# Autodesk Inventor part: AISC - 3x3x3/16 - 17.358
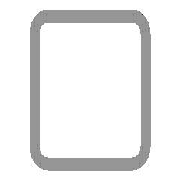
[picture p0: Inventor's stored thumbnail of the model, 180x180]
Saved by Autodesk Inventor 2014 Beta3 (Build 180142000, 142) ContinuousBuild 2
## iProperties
IsCustomPart: 1
Created: 2011-11
Part Number: AISC - 3x3x3/16 - 17.358
Material: Steel, Mild
Description: Tube
Document SubType Name: Modeling
Standard: ANSI
Designer: Thom Tremblay
Standards Organization: ANSI
Language: en-US
Size Designation: 3x3x3/16
Categories: <MemberInstance><Categories><Category DisplayName="Structural Shapes" InternalName="089c4875-fa83-4c05-b084-43b9cc11f5ed" Mnemonic="GRDR"><CategoryParameter Dis
Stock Number: 3x3x3/16
Density: 7.86 g/cm^3
Appearance: Steel
_CCFamilyMember: 9
_CCFamilyDisplayName: ANSI AISC (Square) - Tube
_FrameMemberDoc: Frame Member File
_Version: 15.0.0
_GetPNFromCC: 1
G_L: 17.358 in
G_W: 3.000 in
G_H: 3.000 in
+34C88DA3-0550-4048-8914-D3E873063934+CUTDETAIL3: Cut
+0CA68347-A200-4C89-AB1E-A678EAF8D6F7+CUTDETAIL4: Cut
Author: Thom Tremblay
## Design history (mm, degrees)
node "Start plane"
node "End plane"
node "Driven Length"
  sketch "Sketch3"
    geometry: L1 (0, 0)-(10, 0) reference
    constraints: 2 end point, 1 horizontal
  workplane "Work Plane3"
  sketch "Sketch4"
    geometry: L1 (-2, 0)-(12, 0) reference; L2 (-53.343, 440.904)-(53.343, 440.904) reference
    dimensions: "d19" = 440.90386 distance between parallel lines of L1 L2 (derived)
sketch "Sweep Path"
  geometry: L1 through (609.6, 0) direction (1, 0); 1 other entity
  constraints: 5 horizontal
node "Orientation Work Plane"
feature "Body" dims "d20" = 0
workplane "Work Plane7"
sketch "Sketch7"
  geometry: L1 (-38.6, 38.6)-(38.6, 38.6); L2 (-38.6, -38.6)-(38.6, -38.6)
  constraints: 4 end point
feature "LoftSrf3" sketch "Sketch7" dims "d29" = 0, "d30" = 90 deg, "d31" = 0, "d32" = 90 deg
split "Split3"
workplane "Work Plane8"
sketch "Sketch8"
  geometry: L1 (-38.6, 38.6)-(38.6, 38.6); L2 (-38.6, -38.6)-(38.6, -38.6)
  constraints: 4 end point
feature "LoftSrf4" sketch "Sketch8" dims "d33" = 0, "d34" = 90 deg, "d35" = 0, "d36" = 90 deg
split "Split4"
workplane "Work Plane9"
sketch "Sketch9"
  geometry: L1 (-38.6, 44.506)-(38.6, 44.506); L2 (-38.6, -44.506)-(38.6, -44.506)
  constraints: 4 end point
feature "LoftSrf5" sketch "Sketch9" dims "d37" = 0, "d38" = 90 deg, "d39" = 0, "d40" = 90 deg
split "Split5"
workplane "Work Plane10"
sketch "Sketch10"
  geometry: L1 (-38.6, 44.506)-(38.6, 44.506); L2 (-38.6, -44.506)-(38.6, -44.506)
  constraints: 4 end point
feature "LoftSrf6" sketch "Sketch10" dims "d41" = 0, "d42" = 90 deg, "d43" = 0, "d44" = 90 deg
split "Split6"
body "Solid1"
sketch "Sketch"
  geometry: L1 (-38.1, -28.575)-(-38.1, 28.575); L2 (-28.575, 38.1)-(28.575, 38.1); L3 (38.1, 28.575)-(38.1, -28.575); L4 (28.575, -38.1)-(-28.575, -38.1); L5 (-28.575, 33.337)-(28.575, 33.338); L6 (33.338, 28.575)-(33.338, -28.575); L7 (28.575, -33.337)-(-28.575, -33.338); L8 (-33.338, -28.575)-(-33.338, 28.575); L9 (0, 36.948)-(0, -36.948); L10 (-23.079, 0)-(23.079, 0); A1 r 9.525 centre (-28.575, -28.575) between (-38.1, -28.575) and (-28.575, -38.1); A2 r 9.525 centre (-28.575, 28.575) between (-28.575, 38.1) and (-38.1, 28.575); A3 r 9.525 centre (28.575, 28.575) between (38.1, 28.575) and (28.575, 38.1); A4 r 9.525 centre (28.575, -28.575) between (28.575, -38.1) and (38.1, -28.575); A5 r 4.763 centre (-28.575, 28.575) between (-28.575, 33.337) and (-33.338, 28.575); A6 r 4.763 centre (28.575, 28.575) between (33.338, 28.575) and (28.575, 33.338); A7 r 4.763 centre (28.575, -28.575) between (28.575, -33.337) and (33.338, -28.575); A8 r 4.763 centre (-28.575, -28.575) between (-33.338, -28.575) and (-28.575, -33.338)
  constraints: 20 end point, 16 point on circle, 8 centre point, 8 tangent, 4 parallel, 3 equal radius, 2 perpendicular, 7 other
  dimensions: "d10" = 76.2 distance between parallel lines of L2 L4 (= G_H); "d11" = 76.2 distance between parallel lines of L1 L3 (= G_W); "d12" = 4.7625 distance between parallel lines of L3 L6 (= G_T); "d15" = 38.1 distance between parallel lines of L2 L10 (= 0.5 x d10); "d16" = 38.1 distance between parallel lines of L9 L3 (= 0.5 x d11); "d17" = 9.525 radius of A1 (= G_IR)
body "Srf3"
body "Srf4"
body "Srf5"
body "Srf6"
other parameters: "G_W" = 76.2 [user parameter; used in 1 equation term], "G_H" = 76.2 [user parameter; used in 1 equation term], "G_T" = 4.7625 [user parameter; used in 1 equation term], "G_IR" = 9.525 [user parameter; used in 1 equation term], "G_L" = 440.90386 (= d19) [user parameter], "G_OFFSET_START" = 0 [user parameter; used in 1 equation term], "G_OFFSET_END" = 0 [user parameter; used in 1 equation term], "d13" = 0 (computed from G_OFFSET_START), "d14" = 440.90386 (= G_OFFSET_END + B_L), "B_L" = 440.90386 [user parameter; used in 1 equation term], "d18" = 90 deg
